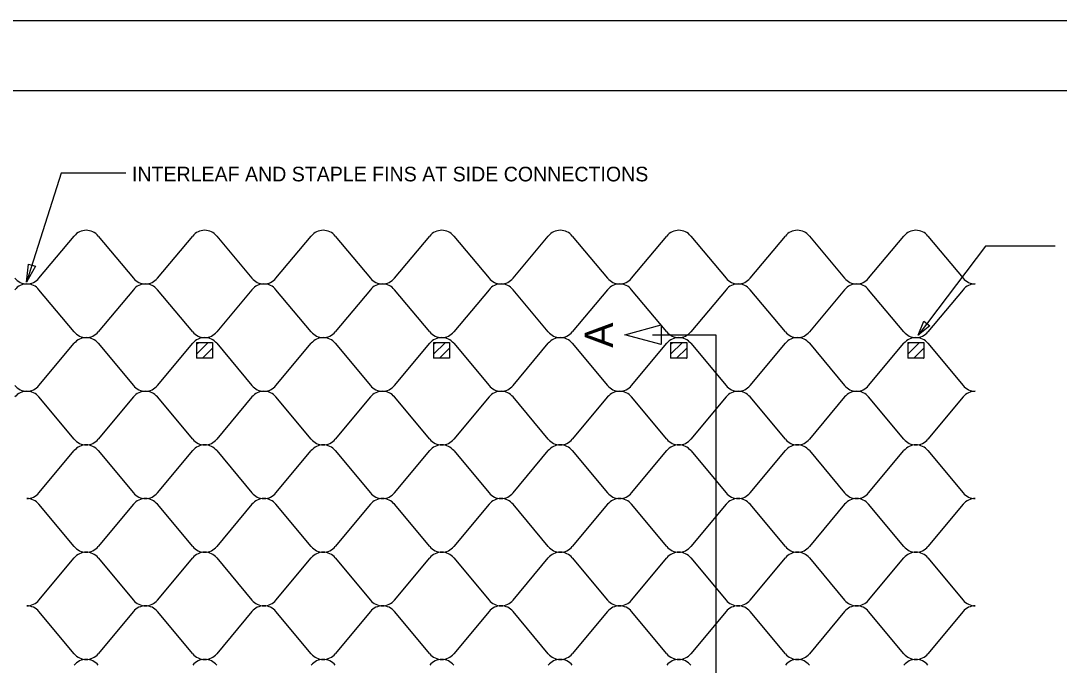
# Model space of a CAD drawing. Extents: x 638850 to 644908, y 297188 to 298900.
# Drawn here: x 641411 to 641612.1, y 297746.5 to 297871.3 of the extents above; entities that cross this region are included whole.
import ezdxf

# ---------------------------------------------------------------- set-up
doc = ezdxf.new("R2010")
doc.units = 0
for name, color, linetype in [('1', 7, 'Continuous'), ('3', 7, 'Continuous'), ('4', 7, 'Continuous'), ('5', 7, 'Continuous'), ('6', 7, 'Continuous')]:
    doc.layers.add(name, color=color, linetype=linetype)

msp = doc.modelspace()

# ---------------------------------------------------------------- linework, layer by layer
at = {"layer": '1'}
for p, q in [((642242.46, 297871.34), (641270.46, 297871.34)), ((641310.96, 297857.84), (642228.96, 297857.84))]:
    msp.add_line(p, q, dxfattribs=at)
at = {"layer": '4'}
for p, q in [((641414.47, 297821.49), (641421.3, 297829.65)), ((641425.95, 297829.65), (641432.78, 297821.49)), ((641437.43, 297821.49), (641444.26, 297829.65)), ((641448.91, 297829.65), (641455.75, 297821.49)), ((641460.4, 297821.49), (641467.23, 297829.65)), ((641471.88, 297829.65), (641478.71, 297821.49)), ((641483.36, 297821.49), (641490.19, 297829.65)), ((641494.84, 297829.65), (641501.67, 297821.49)), ((641506.32, 297821.49), (641513.15, 297829.65)), ((641517.8, 297829.65), (641524.64, 297821.49)), ((641529.29, 297821.49), (641536.12, 297829.65)), ((641540.77, 297829.65), (641547.6, 297821.49)), ((641552.25, 297821.49), (641559.08, 297829.65)), ((641563.73, 297829.65), (641570.56, 297821.49)), ((641575.21, 297821.49), (641582.05, 297829.65)), ((641586.69, 297829.65), (641593.53, 297821.49)), ((641421.3, 297811.1), (641414.47, 297819.26)), ((641432.78, 297819.26), (641425.95, 297811.1)), ((641444.26, 297811.1), (641437.43, 297819.26)), ((641455.75, 297819.26), (641448.91, 297811.1)), ((641467.23, 297811.1), (641460.4, 297819.26)), ((641478.71, 297819.26), (641471.88, 297811.1)), ((641490.19, 297811.1), (641483.36, 297819.26)), ((641501.67, 297819.26), (641494.84, 297811.1)), ((641513.15, 297811.1), (641506.32, 297819.26)), ((641524.64, 297819.26), (641517.8, 297811.1)), ((641536.12, 297811.1), (641529.29, 297819.26)), ((641547.6, 297819.26), (641540.77, 297811.1)), ((641559.08, 297811.1), (641552.25, 297819.26)), ((641570.56, 297819.26), (641563.73, 297811.1)), ((641582.05, 297811.1), (641575.21, 297819.26)), ((641593.53, 297819.26), (641586.69, 297811.1)), ((641414.47, 297800.71), (641421.3, 297808.88)), ((641425.95, 297808.88), (641432.78, 297800.71)), ((641437.43, 297800.71), (641444.26, 297808.88)), ((641448.91, 297808.88), (641455.75, 297800.71)), ((641460.4, 297800.71), (641467.23, 297808.88)), ((641471.88, 297808.88), (641478.71, 297800.71)), ((641483.36, 297800.71), (641490.19, 297808.88)), ((641494.84, 297808.88), (641501.67, 297800.71)), ((641506.32, 297800.71), (641513.15, 297808.88)), ((641517.8, 297808.88), (641524.64, 297800.71)), ((641529.29, 297800.71), (641536.12, 297808.88)), ((641540.77, 297808.88), (641547.6, 297800.71)), ((641552.25, 297800.71), (641559.08, 297808.88)), ((641563.73, 297808.88), (641570.56, 297800.71)), ((641575.21, 297800.71), (641582.05, 297808.88)), ((641586.69, 297808.88), (641593.53, 297800.71)), ((641421.3, 297790.32), (641414.47, 297798.49)), ((641432.78, 297798.49), (641425.95, 297790.32)), ((641444.26, 297790.32), (641437.43, 297798.49)), ((641455.75, 297798.49), (641448.91, 297790.32)), ((641467.23, 297790.32), (641460.4, 297798.49)), ((641478.71, 297798.49), (641471.88, 297790.32)), ((641490.19, 297790.32), (641483.36, 297798.49)), ((641501.67, 297798.49), (641494.84, 297790.32)), ((641513.15, 297790.32), (641506.32, 297798.49)), ((641524.64, 297798.49), (641517.8, 297790.32)), ((641536.12, 297790.32), (641529.29, 297798.49)), ((641547.6, 297798.49), (641540.77, 297790.32)), ((641559.08, 297790.32), (641552.25, 297798.49)), ((641570.56, 297798.49), (641563.73, 297790.32)), ((641582.05, 297790.32), (641575.21, 297798.49)), ((641593.53, 297798.49), (641586.69, 297790.32)), ((641414.47, 297779.93), (641421.3, 297788.1)), ((641425.95, 297788.1), (641432.78, 297779.93)), ((641437.43, 297779.93), (641444.26, 297788.1)), ((641448.91, 297788.1), (641455.75, 297779.93)), ((641460.4, 297779.93), (641467.23, 297788.1)), ((641471.88, 297788.1), (641478.71, 297779.93)), ((641483.36, 297779.93), (641490.19, 297788.1)), ((641494.84, 297788.1), (641501.67, 297779.93)), ((641506.32, 297779.93), (641513.15, 297788.1)), ((641517.8, 297788.1), (641524.64, 297779.93)), ((641529.29, 297779.93), (641536.12, 297788.1)), ((641540.77, 297788.1), (641547.6, 297779.93)), ((641552.25, 297779.93), (641559.08, 297788.1)), ((641563.73, 297788.1), (641570.56, 297779.93)), ((641575.21, 297779.93), (641582.05, 297788.1)), ((641586.69, 297788.1), (641593.53, 297779.93)), ((641421.3, 297769.55), (641414.47, 297777.71)), ((641432.78, 297777.71), (641425.95, 297769.55)), ((641444.26, 297769.55), (641437.43, 297777.71)), ((641455.75, 297777.71), (641448.91, 297769.55)), ((641467.23, 297769.55), (641460.4, 297777.71)), ((641478.71, 297777.71), (641471.88, 297769.55)), ((641490.19, 297769.55), (641483.36, 297777.71)), ((641501.67, 297777.71), (641494.84, 297769.55)), ((641513.15, 297769.55), (641506.32, 297777.71)), ((641524.64, 297777.71), (641517.8, 297769.55)), ((641536.12, 297769.55), (641529.29, 297777.71)), ((641547.6, 297777.71), (641540.77, 297769.55)), ((641559.08, 297769.55), (641552.25, 297777.71)), ((641570.56, 297777.71), (641563.73, 297769.55)), ((641582.05, 297769.55), (641575.21, 297777.71)), ((641593.53, 297777.71), (641586.69, 297769.55)), ((641414.47, 297759.16), (641421.3, 297767.32)), ((641425.95, 297767.32), (641432.78, 297759.16)), ((641437.43, 297759.16), (641444.26, 297767.32)), ((641448.91, 297767.32), (641455.75, 297759.16)), ((641460.4, 297759.16), (641467.23, 297767.32)), ((641471.88, 297767.32), (641478.71, 297759.16)), ((641483.36, 297759.16), (641490.19, 297767.32)), ((641494.84, 297767.32), (641501.67, 297759.16)), ((641506.32, 297759.16), (641513.15, 297767.32)), ((641517.8, 297767.32), (641524.64, 297759.16)), ((641529.29, 297759.16), (641536.12, 297767.32)), ((641540.77, 297767.32), (641547.6, 297759.16)), ((641552.25, 297759.16), (641559.08, 297767.32)), ((641563.73, 297767.32), (641570.56, 297759.16)), ((641575.21, 297759.16), (641582.05, 297767.32)), ((641586.69, 297767.32), (641593.53, 297759.16)), ((641421.3, 297748.77), (641414.47, 297756.93)), ((641432.78, 297756.93), (641425.95, 297748.77)), ((641444.26, 297748.77), (641437.43, 297756.93)), ((641455.75, 297756.93), (641448.91, 297748.77)), ((641467.23, 297748.77), (641460.4, 297756.93)), ((641478.71, 297756.93), (641471.88, 297748.77)), ((641490.19, 297748.77), (641483.36, 297756.93)), ((641501.67, 297756.93), (641494.84, 297748.77)), ((641513.15, 297748.77), (641506.32, 297756.93)), ((641524.64, 297756.93), (641517.8, 297748.77)), ((641536.12, 297748.77), (641529.29, 297756.93)), ((641547.6, 297756.93), (641540.77, 297748.77)), ((641559.08, 297748.77), (641552.25, 297756.93)), ((641570.56, 297756.93), (641563.73, 297748.77)), ((641582.05, 297748.77), (641575.21, 297756.93)), ((641593.53, 297756.93), (641586.69, 297748.77))]:
    msp.add_line(p, q, dxfattribs=at)
for centre, start, end in [((641423.63, 297827.77), 90, 141.0518), ((641423.63, 297827.77), 38.9482, 90), ((641446.59, 297827.77), 90, 141.0518), ((641446.59, 297827.77), 38.9482, 90), ((641469.55, 297827.77), 90, 141.0518), ((641469.55, 297827.77), 38.9482, 90), ((641492.52, 297827.77), 90, 141.0518), ((641492.52, 297827.77), 38.9482, 90), ((641515.48, 297827.77), 90, 141.0518), ((641515.48, 297827.77), 38.9482, 90), ((641538.44, 297827.77), 90, 141.0518), ((641538.44, 297827.77), 38.9482, 90), ((641561.41, 297827.77), 90, 141.0518), ((641561.41, 297827.77), 38.9482, 90), ((641584.37, 297827.77), 90, 141.0518), ((641584.37, 297827.77), 38.9482, 90), ((641412.14, 297823.37), 218.9482, 270), ((641412.14, 297817.39), 90, 141.0518), ((641412.14, 297823.37), 270, 321.0518), ((641412.14, 297817.39), 38.9482, 90), ((641435.11, 297823.37), 218.9482, 270), ((641435.11, 297817.39), 90, 141.0518), ((641435.11, 297823.37), 270, 321.0518), ((641435.11, 297817.39), 38.9482, 90), ((641458.07, 297823.37), 218.9482, 270), ((641458.07, 297817.39), 90, 141.0518), ((641458.07, 297823.37), 270, 321.0518), ((641458.07, 297817.39), 38.9482, 90), ((641481.03, 297823.37), 218.9482, 270), ((641481.03, 297817.39), 90, 141.0518), ((641481.03, 297823.37), 270, 321.0518), ((641481.03, 297817.39), 38.9482, 90), ((641504, 297823.37), 218.9482, 270), ((641504, 297817.39), 90, 141.0518), ((641504, 297823.37), 270, 321.0518), ((641504, 297817.39), 38.9482, 90), ((641526.96, 297823.37), 218.9482, 270), ((641526.96, 297817.39), 90, 141.0518), ((641526.96, 297823.37), 270, 321.0518), ((641526.96, 297817.39), 38.9482, 90), ((641549.92, 297823.37), 218.9482, 270), ((641549.92, 297817.39), 90, 141.0518), ((641549.92, 297823.37), 270, 321.0518), ((641549.92, 297817.39), 38.9482, 90), ((641572.89, 297823.37), 218.9482, 270), ((641572.89, 297817.39), 90, 141.0518), ((641572.89, 297823.37), 270, 321.0518), ((641572.89, 297817.39), 38.9482, 90), ((641595.85, 297823.37), 218.9482, 270), ((641595.85, 297817.39), 90, 141.0518), ((641423.63, 297812.98), 218.9482, 270), ((641423.63, 297807), 90, 141.0518), ((641423.63, 297812.98), 270, 321.0518), ((641423.63, 297807), 38.9482, 90), ((641446.59, 297812.98), 218.9482, 270), ((641446.59, 297807), 90, 141.0518), ((641446.59, 297812.98), 270, 321.0518), ((641446.59, 297807), 38.9482, 90), ((641469.55, 297812.98), 218.9482, 270), ((641469.55, 297807), 90, 141.0518), ((641469.55, 297812.98), 270, 321.0518), ((641469.55, 297807), 38.9482, 90), ((641492.52, 297812.98), 218.9482, 270), ((641492.52, 297807), 90, 141.0518), ((641492.52, 297812.98), 270, 321.0518), ((641492.52, 297807), 38.9482, 90), ((641515.48, 297812.98), 218.9482, 270), ((641515.48, 297807), 90, 141.0518), ((641515.48, 297812.98), 270, 321.0518), ((641515.48, 297807), 38.9482, 90), ((641538.44, 297812.98), 218.9482, 270), ((641538.44, 297807), 90, 141.0518), ((641538.44, 297812.98), 270, 321.0518), ((641538.44, 297807), 38.9482, 90), ((641561.41, 297812.98), 218.9482, 270), ((641561.41, 297807), 90, 141.0518), ((641561.41, 297812.98), 270, 321.0518), ((641561.41, 297807), 38.9482, 90), ((641584.37, 297812.98), 218.9482, 270), ((641584.37, 297807), 90, 141.0518), ((641584.37, 297812.98), 270, 321.0518), ((641584.37, 297807), 38.9482, 90), ((641412.14, 297802.59), 218.9482, 270), ((641412.14, 297802.59), 270, 321.0518), ((641435.11, 297802.59), 218.9482, 270), ((641435.11, 297802.59), 270, 321.0518), ((641458.07, 297802.59), 218.9482, 270), ((641458.07, 297802.59), 270, 321.0518), ((641481.03, 297802.59), 218.9482, 270), ((641481.03, 297802.59), 270, 321.0518), ((641504, 297802.59), 218.9482, 270), ((641504, 297802.59), 270, 321.0518), ((641526.96, 297802.59), 218.9482, 270), ((641526.96, 297802.59), 270, 321.0518), ((641549.92, 297802.59), 218.9482, 270), ((641549.92, 297802.59), 270, 321.0518), ((641572.89, 297802.59), 218.9482, 270), ((641572.89, 297802.59), 270, 321.0518), ((641595.85, 297802.59), 218.9482, 270), ((641412.14, 297796.61), 90, 141.0518), ((641412.14, 297796.61), 38.9482, 90), ((641435.11, 297796.61), 90, 141.0518), ((641435.11, 297796.61), 38.9482, 90), ((641458.07, 297796.61), 90, 141.0518), ((641458.07, 297796.61), 38.9482, 90), ((641481.03, 297796.61), 90, 141.0518), ((641481.03, 297796.61), 38.9482, 90), ((641504, 297796.61), 90, 141.0518), ((641504, 297796.61), 38.9482, 90), ((641526.96, 297796.61), 90, 141.0518), ((641526.96, 297796.61), 38.9482, 90), ((641549.92, 297796.61), 90, 141.0518), ((641549.92, 297796.61), 38.9482, 90), ((641572.89, 297796.61), 90, 141.0518), ((641572.89, 297796.61), 38.9482, 90), ((641595.85, 297796.61), 90, 141.0518), ((641423.63, 297792.2), 218.9482, 270), ((641423.63, 297792.2), 270, 321.0518), ((641446.59, 297792.2), 218.9482, 270), ((641446.59, 297792.2), 270, 321.0518), ((641469.55, 297792.2), 218.9482, 270), ((641469.55, 297792.2), 270, 321.0518), ((641492.52, 297792.2), 218.9482, 270), ((641492.52, 297792.2), 270, 321.0518), ((641515.48, 297792.2), 218.9482, 270), ((641515.48, 297792.2), 270, 321.0518), ((641538.44, 297792.2), 218.9482, 270), ((641538.44, 297792.2), 270, 321.0518), ((641561.41, 297792.2), 218.9482, 270), ((641561.41, 297792.2), 270, 321.0518), ((641584.37, 297792.2), 218.9482, 270), ((641584.37, 297792.2), 270, 321.0518), ((641423.63, 297786.22), 90, 141.0518), ((641423.63, 297786.22), 38.9482, 90), ((641446.59, 297786.22), 90, 141.0518), ((641446.59, 297786.22), 38.9482, 90), ((641469.55, 297786.22), 90, 141.0518), ((641469.55, 297786.22), 38.9482, 90), ((641492.52, 297786.22), 90, 141.0518), ((641492.52, 297786.22), 38.9482, 90), ((641515.48, 297786.22), 90, 141.0518), ((641515.48, 297786.22), 38.9482, 90), ((641538.44, 297786.22), 90, 141.0518), ((641538.44, 297786.22), 38.9482, 90), ((641561.41, 297786.22), 90, 141.0518), ((641561.41, 297786.22), 38.9482, 90), ((641584.37, 297786.22), 90, 141.0518), ((641584.37, 297786.22), 38.9482, 90), ((641412.14, 297781.81), 270, 321.0518), ((641435.11, 297781.81), 218.9482, 270), ((641435.11, 297781.81), 270, 321.0518), ((641458.07, 297781.81), 218.9482, 270), ((641458.07, 297781.81), 270, 321.0518), ((641481.03, 297781.81), 218.9482, 270), ((641481.03, 297781.81), 270, 321.0518), ((641504, 297781.81), 218.9482, 270), ((641504, 297781.81), 270, 321.0518), ((641526.96, 297781.81), 218.9482, 270), ((641526.96, 297781.81), 270, 321.0518), ((641549.92, 297781.81), 218.9482, 270), ((641549.92, 297781.81), 270, 321.0518), ((641572.89, 297781.81), 218.9482, 270), ((641572.89, 297781.81), 270, 321.0518), ((641595.85, 297781.81), 218.9482, 270), ((641412.14, 297775.83), 38.9482, 90), ((641435.11, 297775.83), 90, 141.0518), ((641435.11, 297775.83), 38.9482, 90), ((641458.07, 297775.83), 90, 141.0518), ((641458.07, 297775.83), 38.9482, 90), ((641481.03, 297775.83), 90, 141.0518), ((641481.03, 297775.83), 38.9482, 90), ((641504, 297775.83), 90, 141.0518), ((641504, 297775.83), 38.9482, 90), ((641526.96, 297775.83), 90, 141.0518), ((641526.96, 297775.83), 38.9482, 90), ((641549.92, 297775.83), 90, 141.0518), ((641549.92, 297775.83), 38.9482, 90), ((641572.89, 297775.83), 90, 141.0518), ((641572.89, 297775.83), 38.9482, 90), ((641595.85, 297775.83), 90, 141.0518), ((641423.63, 297771.42), 218.9482, 270), ((641423.63, 297765.44), 90, 141.0518), ((641423.63, 297771.42), 270, 321.0518), ((641423.63, 297765.44), 38.9482, 90), ((641446.59, 297771.42), 218.9482, 270), ((641446.59, 297765.44), 90, 141.0518), ((641446.59, 297771.42), 270, 321.0518), ((641446.59, 297765.44), 38.9482, 90), ((641469.55, 297771.42), 218.9482, 270), ((641469.55, 297765.44), 90, 141.0518), ((641469.55, 297771.42), 270, 321.0518), ((641469.55, 297765.44), 38.9482, 90), ((641492.52, 297771.42), 218.9482, 270), ((641492.52, 297765.44), 90, 141.0518), ((641492.52, 297771.42), 270, 321.0518), ((641492.52, 297765.44), 38.9482, 90), ((641515.48, 297771.42), 218.9482, 270), ((641515.48, 297765.44), 90, 141.0518), ((641515.48, 297771.42), 270, 321.0518), ((641515.48, 297765.44), 38.9482, 90), ((641538.44, 297771.42), 218.9482, 270), ((641538.44, 297765.44), 90, 141.0518), ((641538.44, 297771.42), 270, 321.0518), ((641538.44, 297765.44), 38.9482, 90), ((641561.41, 297771.42), 218.9482, 270), ((641561.41, 297765.44), 90, 141.0518), ((641561.41, 297771.42), 270, 321.0518), ((641561.41, 297765.44), 38.9482, 90), ((641584.37, 297771.42), 218.9482, 270), ((641584.37, 297765.44), 90, 141.0518), ((641584.37, 297771.42), 270, 321.0518), ((641584.37, 297765.44), 38.9482, 90), ((641412.14, 297761.04), 270, 321.0518), ((641412.14, 297755.06), 38.9482, 90), ((641435.11, 297761.04), 218.9482, 270), ((641435.11, 297755.06), 90, 141.0518), ((641435.11, 297761.04), 270, 321.0518), ((641435.11, 297755.06), 38.9482, 90), ((641458.07, 297761.04), 218.9482, 270), ((641458.07, 297755.06), 90, 141.0518), ((641458.07, 297761.04), 270, 321.0518), ((641458.07, 297755.06), 38.9482, 90), ((641481.03, 297761.04), 218.9482, 270), ((641481.03, 297755.06), 90, 141.0518), ((641481.03, 297761.04), 270, 321.0518), ((641481.03, 297755.06), 38.9482, 90), ((641504, 297761.04), 218.9482, 270), ((641504, 297755.06), 90, 141.0518), ((641504, 297761.04), 270, 321.0518), ((641504, 297755.06), 38.9482, 90), ((641526.96, 297761.04), 218.9482, 270), ((641526.96, 297755.06), 90, 141.0518), ((641526.96, 297761.04), 270, 321.0518), ((641526.96, 297755.06), 38.9482, 90), ((641549.92, 297761.04), 218.9482, 270), ((641549.92, 297755.06), 90, 141.0518), ((641549.92, 297761.04), 270, 321.0518), ((641549.92, 297755.06), 38.9482, 90), ((641572.89, 297761.04), 218.9482, 270), ((641572.89, 297755.06), 90, 141.0518), ((641572.89, 297761.04), 270, 321.0518), ((641572.89, 297755.06), 38.9482, 90), ((641595.85, 297761.04), 218.9482, 270), ((641595.85, 297755.06), 90, 141.0518), ((641423.63, 297750.65), 218.9482, 270), ((641423.63, 297744.67), 90, 141.0518), ((641423.63, 297750.65), 270, 321.0518), ((641423.63, 297744.67), 38.9482, 90), ((641446.59, 297750.65), 218.9482, 270), ((641446.59, 297744.67), 90, 141.0518), ((641446.59, 297750.65), 270, 321.0518), ((641446.59, 297744.67), 38.9482, 90), ((641469.55, 297750.65), 218.9482, 270), ((641469.55, 297744.67), 90, 141.0518), ((641469.55, 297750.65), 270, 321.0518), ((641469.55, 297744.67), 38.9482, 90), ((641492.52, 297750.65), 218.9482, 270), ((641492.52, 297744.67), 90, 141.0518), ((641492.52, 297750.65), 270, 321.0518), ((641492.52, 297744.67), 38.9482, 90), ((641515.48, 297750.65), 218.9482, 270), ((641515.48, 297744.67), 90, 141.0518), ((641515.48, 297750.65), 270, 321.0518), ((641515.48, 297744.67), 38.9482, 90), ((641538.44, 297750.65), 218.9482, 270), ((641538.44, 297744.67), 90, 141.0518), ((641538.44, 297750.65), 270, 321.0518), ((641538.44, 297744.67), 38.9482, 90), ((641561.41, 297750.65), 218.9482, 270), ((641561.41, 297744.67), 90, 141.0518), ((641561.41, 297750.65), 270, 321.0518), ((641561.41, 297744.67), 38.9482, 90), ((641584.37, 297750.65), 218.9482, 270), ((641584.37, 297744.67), 90, 141.0518), ((641584.37, 297750.65), 270, 321.0518), ((641584.37, 297744.67), 38.9482, 90)]:
    msp.add_arc(centre, 2.99, start, end, dxfattribs=at)
at = {"layer": '5'}
for p, q in [((641418.79, 297841.83), (641412.1, 297820.71)), ((641431.32, 297841.83), (641418.79, 297841.83)), ((641597.85, 297827.68), (641584.79, 297810.48)), ((641611.33, 297827.68), (641597.85, 297827.68)), ((641533.36, 297810.51), (641545.62, 297810.51)), ((641545.62, 297810.51), (641545.62, 297664.71))]:
    msp.add_line(p, q, dxfattribs=at)
for points in [[(641413.83, 297823.8), (641412.1, 297820.71), (641412.48, 297824.23)], [(641535.01, 297808.65), (641527.98, 297810.54), (641535.01, 297812.43)], [(641587.05, 297812.28), (641584.79, 297810.48), (641585.92, 297813.14)]]:
    msp.add_lwpolyline(points, close=True, dxfattribs=at)
at = {"layer": '6'}
for p, q in [((641445, 297809.05), (641448.11, 297809.05)), ((641445, 297809.05), (641445, 297805.99)), ((641445, 297806.77), (641447.29, 297809.05)), ((641445, 297808.7), (641445.36, 297809.05)), ((641448.11, 297809.05), (641448.11, 297805.99)), ((641490.93, 297809.05), (641494.03, 297809.05)), ((641490.93, 297809.05), (641490.93, 297805.99)), ((641490.93, 297806.77), (641493.22, 297809.05)), ((641490.93, 297808.7), (641491.28, 297809.05)), ((641494.03, 297809.05), (641494.03, 297805.99)), ((641536.86, 297809.05), (641539.96, 297809.05)), ((641536.86, 297809.05), (641536.86, 297805.99)), ((641536.86, 297806.77), (641539.14, 297809.05)), ((641536.86, 297808.7), (641537.21, 297809.05)), ((641539.96, 297809.05), (641539.96, 297805.99)), ((641582.79, 297809.05), (641585.89, 297809.05)), ((641582.79, 297809.05), (641582.79, 297805.99)), ((641582.79, 297806.77), (641585.07, 297809.05)), ((641582.79, 297808.7), (641583.14, 297809.05)), ((641585.89, 297809.05), (641585.89, 297805.99)), ((641448.11, 297805.99), (641445, 297805.99)), ((641446.16, 297805.99), (641448.11, 297807.94)), ((641448.09, 297805.99), (641448.11, 297806)), ((641494.03, 297805.99), (641490.93, 297805.99)), ((641492.09, 297805.99), (641494.03, 297807.94)), ((641494.02, 297805.99), (641494.03, 297806)), ((641539.96, 297805.99), (641536.86, 297805.99)), ((641538.01, 297805.99), (641539.96, 297807.94)), ((641539.95, 297805.99), (641539.96, 297806)), ((641585.89, 297805.99), (641582.79, 297805.99)), ((641583.94, 297805.99), (641585.89, 297807.94)), ((641585.87, 297805.99), (641585.89, 297806))]:
    msp.add_line(p, q, dxfattribs=at)

# ---------------------------------------------------------------- texts
at = {"layer": '3'}
msp.add_text('INTERLEAF AND STAPLE FINS AT SIDE CONNECTIONS ', height=2.8341, dxfattribs=at).set_placement((641432.5, 297840.24))
at = {"layer": '5'}
msp.add_text('A', height=5.45, rotation=90, dxfattribs=at).set_placement((641525.67, 297808.04))

doc.saveas('drawing.dxf')
